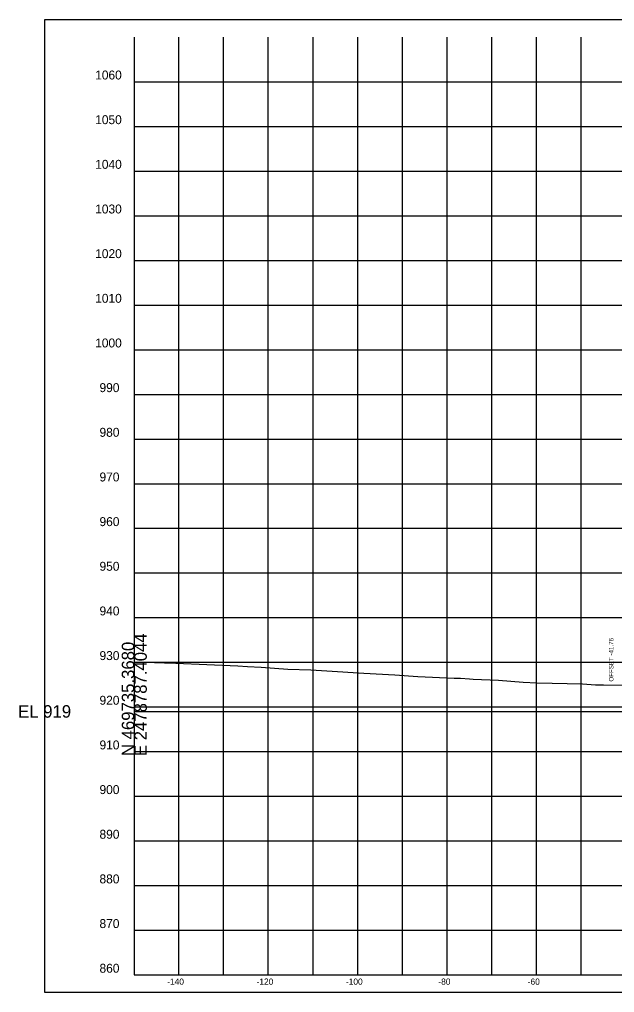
# Model space of a CAD drawing. Extents: x -26 to 2478923, y -10 to 469990.
# Drawn here: x -25.7 to 107.5, y 3937.1 to 4154.9 of the extents above; entities that cross this region are included whole.
import ezdxf

# ---------------------------------------------------------------- set-up
doc = ezdxf.new("R2010")
doc.units = 0
for name, color, linetype in [('DESIGN - SHEET - Corner Text', 7, 'Continuous'), ('DESIGN - SHEET - Light Grid', 7, 'Continuous'), ('DESIGN - SHEET - Linework', 7, 'Continuous'), ('DESIGN - SHEET - Plot Shape', 7, 'Continuous'), ('DESIGN - TYPICAL - Slope Tie Text', 7, 'Continuous'), ('SURVEY - GROUND - Top of Ground', 7, 'Continuous')]:
    doc.layers.add(name, color=color, linetype=linetype)

msp = doc.modelspace()

# ---------------------------------------------------------------- linework, layer by layer
at = {"layer": 'DESIGN - SHEET - Light Grid'}
msp.add_line((0, 4000), (150, 4000), dxfattribs=at)
at = {"layer": 'DESIGN - SHEET - Linework'}
for p, q in [((10, 3941), (10, 4151)), ((10, 3941), (10, 4151)), ((10, 3941), (10, 4151)), ((10, 3941), (10, 4151)), ((20, 3941), (20, 4151)), ((20, 3941), (20, 4151)), ((20, 3941), (20, 4151)), ((20, 3941), (20, 4151)), ((30, 3941), (30, 4151)), ((30, 3941), (30, 4151)), ((30, 3941), (30, 4151)), ((30, 3941), (30, 4151)), ((40, 3941), (40, 4151)), ((40, 3941), (40, 4151)), ((40, 3941), (40, 4151)), ((40, 3941), (40, 4151)), ((50, 3941), (50, 4151)), ((50, 3941), (50, 4151)), ((50, 3941), (50, 4151)), ((50, 3941), (50, 4151)), ((60, 3941), (60, 4151)), ((60, 3941), (60, 4151)), ((60, 3941), (60, 4151)), ((60, 3941), (60, 4151)), ((70, 3941), (70, 4151)), ((70, 3941), (70, 4151)), ((70, 3941), (70, 4151)), ((70, 3941), (70, 4151)), ((80, 3941), (80, 4151)), ((80, 3941), (80, 4151)), ((80, 3941), (80, 4151)), ((80, 3941), (80, 4151)), ((90, 3941), (90, 4151)), ((90, 3941), (90, 4151)), ((90, 3941), (90, 4151)), ((90, 3941), (90, 4151)), ((100, 3941), (100, 4151)), ((100, 3941), (100, 4151)), ((100, 3941), (100, 4151)), ((100, 3941), (100, 4151)), ((0, 4141), (300, 4141)), ((0, 4141), (300, 4141)), ((0, 4141), (300, 4141)), ((0, 4141), (300, 4141)), ((0, 4131), (300, 4131)), ((0, 4131), (300, 4131)), ((0, 4131), (300, 4131)), ((0, 4131), (300, 4131)), ((0, 4121), (300, 4121)), ((0, 4121), (300, 4121)), ((0, 4121), (300, 4121)), ((0, 4121), (300, 4121)), ((0, 4111), (300, 4111)), ((0, 4111), (300, 4111)), ((0, 4111), (300, 4111)), ((0, 4111), (300, 4111)), ((0, 4101), (300, 4101)), ((0, 4101), (300, 4101)), ((0, 4101), (300, 4101)), ((0, 4101), (300, 4101)), ((0, 4091), (300, 4091)), ((0, 4091), (300, 4091)), ((0, 4091), (300, 4091)), ((0, 4091), (300, 4091)), ((0, 4081), (300, 4081)), ((0, 4081), (300, 4081)), ((0, 4081), (300, 4081)), ((0, 4081), (300, 4081)), ((0, 4071), (300, 4071)), ((0, 4071), (300, 4071)), ((0, 4071), (300, 4071)), ((0, 4071), (300, 4071)), ((0, 4061), (300, 4061)), ((0, 4061), (300, 4061)), ((0, 4061), (300, 4061)), ((0, 4061), (300, 4061)), ((0, 4051), (300, 4051)), ((0, 4051), (300, 4051)), ((0, 4051), (300, 4051)), ((0, 4051), (300, 4051)), ((0, 4041), (300, 4041)), ((0, 4041), (300, 4041)), ((0, 4041), (300, 4041)), ((0, 4041), (300, 4041)), ((0, 4031), (300, 4031)), ((0, 4031), (300, 4031)), ((0, 4031), (300, 4031)), ((0, 4031), (300, 4031)), ((0, 4021), (300, 4021)), ((0, 4021), (300, 4021)), ((0, 4021), (300, 4021)), ((0, 4021), (300, 4021)), ((0, 4011), (300, 4011)), ((0, 4011), (300, 4011)), ((0, 4011), (300, 4011)), ((0, 4011), (300, 4011)), ((0, 4001), (300, 4001)), ((0, 4001), (300, 4001)), ((0, 4001), (300, 4001)), ((0, 4001), (300, 4001)), ((0, 3991), (300, 3991)), ((0, 3991), (300, 3991)), ((0, 3991), (300, 3991)), ((0, 3991), (300, 3991)), ((0, 3981), (300, 3981)), ((0, 3981), (300, 3981)), ((0, 3981), (300, 3981)), ((0, 3981), (300, 3981)), ((0, 3971), (300, 3971)), ((0, 3971), (300, 3971)), ((0, 3971), (300, 3971)), ((0, 3971), (300, 3971)), ((0, 3961), (300, 3961)), ((0, 3961), (300, 3961)), ((0, 3961), (300, 3961)), ((0, 3961), (300, 3961)), ((0, 3951), (300, 3951)), ((0, 3951), (300, 3951)), ((0, 3951), (300, 3951)), ((0, 3951), (300, 3951))]:
    msp.add_line(p, q, dxfattribs=at)
msp.add_lwpolyline([(0, 4151), (0, 3941), (300, 3941), (300, 4151)], dxfattribs=at)
msp.add_lwpolyline([(0, 4151), (0, 3941), (300, 3941), (300, 4151)], dxfattribs=at)
msp.add_lwpolyline([(0, 4151), (0, 3941), (300, 3941), (300, 4151)], dxfattribs=at)
msp.add_lwpolyline([(0, 4151), (0, 3941), (300, 3941), (300, 4151)], dxfattribs=at)
at = {"layer": 'DESIGN - SHEET - Plot Shape'}
msp.add_lwpolyline([(-20, 4154.94), (320, 4154.94), (320, 3937.06), (-20, 3937.06)], close=True, dxfattribs=at)
msp.add_lwpolyline([(-20, 4154.94), (320, 4154.94), (320, 3937.06), (-20, 3937.06)], close=True, dxfattribs=at)
msp.add_lwpolyline([(-20, 4154.94), (320, 4154.94), (320, 3937.06), (-20, 3937.06)], close=True, dxfattribs=at)
msp.add_lwpolyline([(-20, 4154.94), (320, 4154.94), (320, 3937.06), (-20, 3937.06)], close=True, dxfattribs=at)
at = {"layer": 'SURVEY - GROUND - Top of Ground'}
msp.add_line((9.27, 4010.82), (23.18, 4010.2), dxfattribs=at)
for points in [[(0, 4011.09), (6.74, 4010.89), (9.27, 4010.82)], [(23.18, 4010.2), (25.31, 4010.07), (28.38, 4009.88), (34.39, 4009.5), (39.51, 4009.28), (43.11, 4009.06), (51.38, 4008.56), (58.31, 4008.18), (63.49, 4007.8), (71.59, 4007.42), (73, 4007.44), (75.01, 4007.31), (75.83, 4007.23), (81.53, 4006.98), (87, 4006.58), (90.09, 4006.42), (100.31, 4006.16), (103.24, 4005.99), (105, 4005.96), (117.03, 4005.88)]]:
    msp.add_lwpolyline(points, dxfattribs=at)

# ---------------------------------------------------------------- texts
at = {"layer": 'DESIGN - SHEET - Corner Text'}
for s, height, p in [('1060', 2, (-8.75, 4141.5)), ('1060', 2, (-8.75, 4141.5)), ('1060', 2, (-8.75, 4141.5)), ('1060', 2, (-8.75, 4141.5)), ('1050', 2, (-8.75, 4131.5)), ('1050', 2, (-8.75, 4131.5)), ('1050', 2, (-8.75, 4131.5)), ('1050', 2, (-8.75, 4131.5)), ('1040', 2, (-8.75, 4121.5)), ('1040', 2, (-8.75, 4121.5)), ('1040', 2, (-8.75, 4121.5)), ('1040', 2, (-8.75, 4121.5)), ('1030', 2, (-8.75, 4111.5)), ('1030', 2, (-8.75, 4111.5)), ('1030', 2, (-8.75, 4111.5)), ('1030', 2, (-8.75, 4111.5)), ('1020', 2, (-8.75, 4101.5)), ('1020', 2, (-8.75, 4101.5)), ('1020', 2, (-8.75, 4101.5)), ('1020', 2, (-8.75, 4101.5)), ('1010', 2, (-8.75, 4091.5)), ('1010', 2, (-8.75, 4091.5)), ('1010', 2, (-8.75, 4091.5)), ('1010', 2, (-8.75, 4091.5)), ('1000', 2, (-8.75, 4081.5)), ('1000', 2, (-8.75, 4081.5)), ('1000', 2, (-8.75, 4081.5)), ('1000', 2, (-8.75, 4081.5)), ('990', 2, (-7.78, 4071.5)), ('990', 2, (-7.78, 4071.5)), ('990', 2, (-7.78, 4071.5)), ('990', 2, (-7.78, 4071.5)), ('980', 2, (-7.78, 4061.5)), ('980', 2, (-7.78, 4061.5)), ('980', 2, (-7.78, 4061.5)), ('980', 2, (-7.78, 4061.5)), ('970', 2, (-7.78, 4051.5)), ('970', 2, (-7.78, 4051.5)), ('970', 2, (-7.78, 4051.5)), ('970', 2, (-7.78, 4051.5)), ('960', 2, (-7.78, 4041.5)), ('960', 2, (-7.78, 4041.5)), ('960', 2, (-7.78, 4041.5)), ('960', 2, (-7.78, 4041.5)), ('950', 2, (-7.78, 4031.5)), ('950', 2, (-7.78, 4031.5)), ('950', 2, (-7.78, 4031.5)), ('950', 2, (-7.78, 4031.5)), ('940', 2, (-7.78, 4021.5)), ('940', 2, (-7.78, 4021.5)), ('940', 2, (-7.78, 4021.5)), ('940', 2, (-7.78, 4021.5)), ('930', 2, (-7.78, 4011.5)), ('930', 2, (-7.78, 4011.5)), ('930', 2, (-7.78, 4011.5)), ('930', 2, (-7.78, 4011.5)), ('920', 2, (-7.78, 4001.5)), ('920', 2, (-7.78, 4001.5)), ('920', 2, (-7.78, 4001.5)), ('920', 2, (-7.78, 4001.5)), ('910', 2, (-7.78, 3991.5)), ('910', 2, (-7.78, 3991.5)), ('910', 2, (-7.78, 3991.5)), ('910', 2, (-7.78, 3991.5)), ('900', 2, (-7.78, 3981.5)), ('900', 2, (-7.78, 3981.5)), ('900', 2, (-7.78, 3981.5)), ('900', 2, (-7.78, 3981.5)), ('890', 2, (-7.78, 3971.5)), ('890', 2, (-7.78, 3971.5)), ('890', 2, (-7.78, 3971.5)), ('890', 2, (-7.78, 3971.5)), ('880', 2, (-7.78, 3961.5)), ('880', 2, (-7.78, 3961.5)), ('880', 2, (-7.78, 3961.5)), ('880', 2, (-7.78, 3961.5)), ('870', 2, (-7.78, 3951.5)), ('870', 2, (-7.78, 3951.5)), ('870', 2, (-7.78, 3951.5)), ('870', 2, (-7.78, 3951.5)), ('860', 2, (-7.78, 3941.5)), ('860', 2, (-7.78, 3941.5)), ('860', 2, (-7.78, 3941.5)), ('860', 2, (-7.78, 3941.5)), ('-140', 1.4, (7.37, 3938.8)), ('-140', 1.4, (7.37, 3938.8)), ('-140', 1.4, (7.37, 3938.8)), ('-140', 1.4, (7.37, 3938.8)), ('-120', 1.4, (27.37, 3938.8)), ('-120', 1.4, (27.37, 3938.8)), ('-120', 1.4, (27.37, 3938.8)), ('-120', 1.4, (27.37, 3938.8)), ('-100', 1.4, (47.37, 3938.8)), ('-100', 1.4, (47.37, 3938.8)), ('-100', 1.4, (47.37, 3938.8)), ('-100', 1.4, (47.37, 3938.8)), ('-80', 1.4, (68.06, 3938.8)), ('-80', 1.4, (68.06, 3938.8)), ('-80', 1.4, (68.06, 3938.8)), ('-80', 1.4, (68.06, 3938.8)), ('-60', 1.4, (88.06, 3938.8)), ('-60', 1.4, (88.06, 3938.8)), ('-60', 1.4, (88.06, 3938.8)), ('-60', 1.4, (88.06, 3938.8))]:
    msp.add_text(s, height=height, dxfattribs=at).set_placement(p)
at = {"layer": 'DESIGN - SHEET - Light Grid'}
for s, p in [('E 2478787.4044', (2.8, 3990)), ('N 469735.3680', (0, 3990))]:
    msp.add_text(s, height=2.8, rotation=90, dxfattribs=at).set_placement(p)
msp.add_text('EL 919', height=2.8, dxfattribs=at).set_placement((-26, 3998.6))
at = {"layer": 'DESIGN - TYPICAL - Slope Tie Text'}
msp.add_text('OFFSET -41.76', height=1, rotation=90, dxfattribs=at).set_placement((107.24, 4006.69))

doc.saveas('drawing.dxf')
